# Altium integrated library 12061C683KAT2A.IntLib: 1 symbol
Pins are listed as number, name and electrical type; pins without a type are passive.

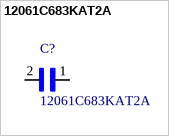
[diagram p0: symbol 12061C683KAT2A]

## 12061C683KAT2A
designator C?
1206 68 nF 100 V Â±10 % Tolerance X7R Surface Mount Multilayer Ceramic Capacitor; MF: AVX
footprint CAPC320160X94
pins: 1, 2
